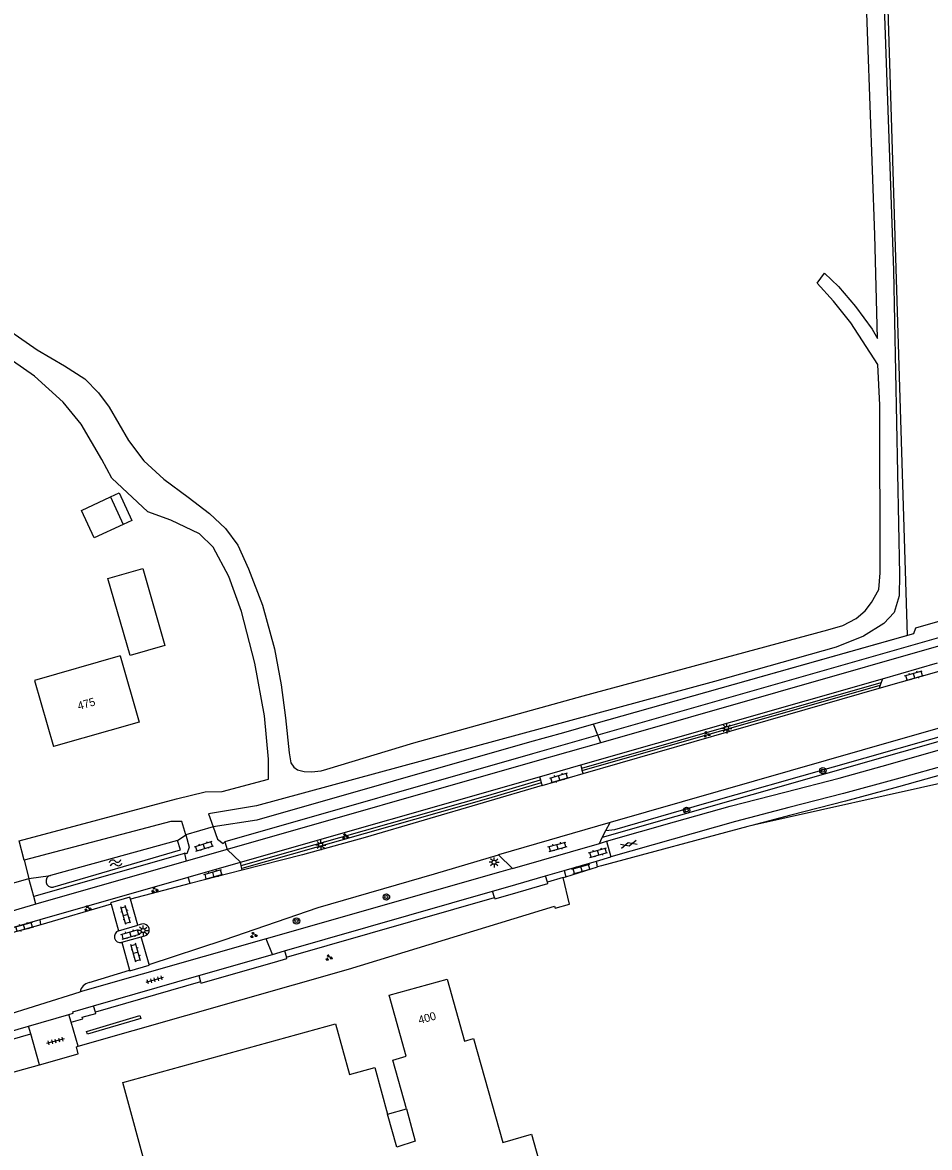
# Model space of a CAD drawing. Extents: x 124000 to 129000, y 395500 to 397503.
# Drawn here: x 127722.2 to 127835.6, y 395651.7 to 395792.3 of the extents above; entities that cross this region are included whole.
import ezdxf

# ---------------------------------------------------------------- set-up
doc = ezdxf.new("R2010")
doc.units = 0
for name, color, linetype in [('gg-afsc-hekwerk', 7, 'Continuous'), ('gg-anno-huisnummerreeks BGT', 7, 'Continuous'), ('gg-bbg-bijgebouw', 7, 'Continuous'), ('gg-bbg-gedigitaliseerde bebouwing', 7, 'Continuous'), ('gg-bbg-gedigitaliseerde bijgebouw', 7, 'Continuous'), ('gg-bbg-hoofdgebouw', 7, 'Continuous'), ('gg-bbg-luifel en loopbrug', 7, 'Continuous'), ('gg-knt-onverhard', 7, 'Continuous'), ('gg-knt-verharding', 7, 'Continuous'), ('gg-kntw-bovenkant insteek waterloop', 7, 'Continuous'), ('gt-grn-groengrens', 7, 'Continuous'), ('gt-grn-groengrens NZ', 7, 'Continuous'), ('gt-grn-weggrens', 7, 'Continuous'), ('gt-symb-boom', 7, 'Continuous'), ('gt-symb-gesloten verharding', 7, 'Continuous'), ('gt-symb-groenvak', 7, 'Continuous'), ('gt-symb-klinker verharding', 7, 'Continuous'), ('gt-symb-lichtmast', 7, 'Continuous'), ('gt-symb-tegel verharding', 7, 'Continuous'), ('gt-symb-watersymbool', 7, 'Continuous')]:
    doc.layers.add(name, color=color, linetype=linetype)

# ---------------------------------------------------------------- blocks, each defined once
blk = doc.blocks.new('gt0-KL1')
at = {"layer": 'gt-symb-klinker verharding'}
for p, q in [((-1.15, 0.3), (1.15, 0.3)), ((-1, -0.3), (-1, 0.3)), ((-0.5, 0.3), (-0.5, 0.45)), ((0, -0.3), (0, 0.3)), ((0.5, 0.3), (0.5, 0.45)), ((1, -0.3), (1, 0.3)), ((-1.15, -0.3), (1.15, -0.3)), ((-0.5, -0.45), (-0.5, -0.3)), ((0.5, -0.45), (0.5, -0.3))]:
    blk.add_line(p, q, dxfattribs=at)
blk = doc.blocks.new('gt0-TEG1')
at = {"layer": 'gt-symb-tegel verharding'}
for p, q in [((-1.12, 0), (1.13, 0)), ((-0.9, -0.25), (-0.9, 0.25)), ((-0.45, -0.25), (-0.45, 0.25)), ((0, -0.25), (0, 0.25)), ((0.45, -0.25), (0.45, 0.25)), ((0.9, -0.25), (0.9, 0.25))]:
    blk.add_line(p, q, dxfattribs=at)
blk = doc.blocks.new('gt0-BOOM')
at = {"layer": 'gt-symb-boom'}
for radius in [0.4, 0.2]:
    blk.add_circle((0, 0), radius, dxfattribs=at)
blk = doc.blocks.new('gt0-GESVH1')
at = {"layer": 'gt-symb-gesloten verharding'}
for p, q in [((-0.99, -0.26), (0.01, 0.24)), ((0.01, -0.26), (-0.99, 0.24)), ((0.01, 0.24), (1.01, -0.26)), ((1.01, 0.24), (0.01, -0.26))]:
    blk.add_line(p, q, dxfattribs=at)
blk = doc.blocks.new('gt0-GRVAK')
at = {"layer": 'gt-symb-groenvak'}
for p, q in [((-0.11, 0.19), (-0.23, 0.24)), ((-0.18, 0.15), (0.09, 0.15)), ((-0.09, 0.21), (-0.16, 0.32)), ((-0.05, 0.21), (-0.05, 0.39)), ((0, 0.21), (0.06, 0.32)), ((0.01, 0.19), (0.13, 0.24)), ((0.26, -0.05), (0.2, 0.06)), ((0.3, -0.05), (0.3, 0.13)), ((0.35, -0.05), (0.41, 0.06)), ((-0.25, -0.23), (-0.36, -0.18)), ((-0.32, -0.26), (-0.05, -0.26)), ((-0.23, -0.21), (-0.29, -0.09)), ((-0.18, -0.2), (-0.18, -0.02)), ((-0.14, -0.21), (-0.07, -0.09)), ((-0.12, -0.23), (0, -0.18)), ((0.24, -0.07), (0.12, -0.02)), ((0.17, -0.11), (0.44, -0.11)), ((0.37, -0.07), (0.49, -0.02))]:
    blk.add_line(p, q, dxfattribs=at)
blk = doc.blocks.new('gt0-LMAST')
at = {"layer": 'gt-symb-lichtmast'}
for p, q in [((-0.18, 0.17), (-0.45, 0.44)), ((-0.01, 0.25), (-0.01, 0.62)), ((0.17, 0.17), (0.44, 0.44)), ((-0.26, 0), (-0.63, 0)), ((-0.18, -0.18), (-0.45, -0.45)), ((-0.01, -0.25), (-0.01, -0.63)), ((0.44, -0.45), (0.17, -0.18)), ((0.24, 0), (0.62, 0))]:
    blk.add_line(p, q, dxfattribs=at)
blk.add_circle((-0.01, 0), 0.25, dxfattribs=at)
blk = doc.blocks.new('gt0-WA')
at = {"layer": 'gt-symb-watersymbool'}
for centre, start, end in [((-0.32, 0.02), 28.0725, 151.9275), ((0.43, 0.42), 208.0725, 331.9275), ((-0.32, -0.43), 28.0725, 151.9275), ((0.43, -0.03), 208.0725, 331.9275)]:
    blk.add_arc(centre, 0.425, start, end, dxfattribs=at)

msp = doc.modelspace()

# ---------------------------------------------------------------- linework, layer by layer
at = {"layer": 'gg-afsc-hekwerk'}
for p, q in [((127833.56, 395715.9), (127793.59, 395704.6)), ((127832.82, 395715.69), (127793.59, 395704.6)), ((127833.56, 395715.9), (127832.82, 395715.69)), ((127793.59, 395704.6), (127789.82, 395703.54)), ((127793.59, 395704.6), (127789.82, 395703.54)), ((127789.82, 395703.54), (127785.57, 395702.36)), ((127789.82, 395703.54), (127785.57, 395702.36)), ((127867.01, 395703.93), (127813.34, 395691.94)), ((127746.06, 395691.8), (127742.62, 395690.8)), ((127746.06, 395691.8), (127742.62, 395690.8)), ((127790.13, 395685.55), (127794.07, 395686.77)), ((127789.77, 395685.44), (127790.13, 395685.55))]:
    msp.add_line(p, q, dxfattribs=at)
for points in [[(127926.73, 395743.24), (127884.31, 395731.12), (127883.52, 395734.03), (127880.23, 395733.04), (127881.06, 395730.15), (127833.81, 395716.63), (127833.56, 395715.9)], [(127880.23, 395733.04), (127881.06, 395730.15), (127833.81, 395716.63), (127833.56, 395715.9)], [(127785.57, 395702.36), (127751.51, 395692.62), (127746.06, 395691.8)], [(127785.57, 395702.36), (127751.51, 395692.62), (127746.06, 395691.8)], [(127813.34, 395691.94), (127812.84, 395691.83), (127794.55, 395686.92), (127794.07, 395686.77)], [(127729.16, 395664.36), (127762.95, 395674), (127788.68, 395681.85), (127788.76, 395681.62), (127790.57, 395682.14), (127789.77, 395685.44)], [(127724.35, 395662.06), (127729.18, 395663.4), (127728.95, 395664.3), (127729.16, 395664.36)], [(127714.67, 395660.36), (127714.96, 395659.46), (127724.35, 395662.06)]]:
    msp.add_lwpolyline(points, dxfattribs=at)
at = {"layer": 'gg-bbg-bijgebouw'}
msp.add_line((127740.01, 395714.45), (127735.67, 395713.2), dxfattribs=at)
at = {"layer": 'gg-bbg-gedigitaliseerde bebouwing'}
msp.add_lwpolyline([(127734.41, 395713.14), (127723.74, 395710.08), (127726.08, 395701.84)], dxfattribs=at)
at = {"layer": 'gg-bbg-gedigitaliseerde bijgebouw'}
msp.add_line((127733.2, 395733.01), (127734.81, 395729.57), dxfattribs=at)
for points in [[(127734.81, 395729.57), (127731.19, 395727.88), (127729.58, 395731.32), (127733.2, 395733.01)], [(127735.67, 395713.2), (127732.9, 395722.81), (127737.24, 395724.06), (127740.01, 395714.45)]]:
    msp.add_lwpolyline(points, dxfattribs=at)
at = {"layer": 'gg-bbg-hoofdgebouw'}
for points in [[(127734.41, 395713.14), (127736.78, 395704.88), (127726.08, 395701.84)], [(127770.19, 395656.53), (127768.51, 395662.62), (127770.18, 395663.11), (127768.02, 395670.74), (127775.3, 395672.76), (127777.44, 395665), (127778.58, 395665.35), (127782.24, 395652.34), (127785.82, 395653.36), (127787.38, 395647.89)], [(127737.94, 395648.22), (127734.74, 395659.83), (127761.34, 395667.16), (127763.09, 395660.82), (127766.24, 395661.69), (127767.84, 395655.88)], [(127770.19, 395656.53), (127771.3, 395652.49), (127768.98, 395651.76), (127767.84, 395655.88)]]:
    msp.add_lwpolyline(points, dxfattribs=at)
at = {"layer": 'gg-bbg-luifel en loopbrug'}
msp.add_line((127767.84, 395655.88), (127770.19, 395656.53), dxfattribs=at)
msp.add_lwpolyline([(127733.2, 395733.01), (127734.28, 395733.52), (127735.9, 395730.08), (127734.81, 395729.57)], dxfattribs=at)
at = {"layer": 'gg-knt-onverhard'}
msp.add_line((127722.45, 395687.61), (127723.01, 395685.31), dxfattribs=at)
for points in [[(127821.9, 395982.58), (127826.07, 395878.37), (127827.36, 395860.58), (127829.47, 395806.14), (127831.06, 395761.29), (127831.82, 395723.3), (127831.76, 395720.66), (127831.12, 395718.55), (127829.83, 395717.2), (127827.3, 395715.61), (127823.87, 395714.24), (127808.67, 395709.95), (127751.47, 395694.41), (127745.46, 395693.4), (127746.06, 395691.8)], [(127718.4, 395755.29), (127724.04, 395751.39), (127727.46, 395749.41), (127730, 395747.77), (127731.7, 395746.02), (127733.04, 395744.25), (127735.47, 395740.05), (127737.37, 395737.51), (127739.88, 395735.24), (127742.91, 395732.98), (127745.57, 395730.93), (127747.6, 395729.05), (127749.13, 395727), (127750.47, 395724.03), (127752.22, 395719.5), (127753.73, 395714.02), (127754.56, 395709.55), (127755.08, 395705.39), (127755.54, 395701.04), (127755.73, 395699.78), (127756.13, 395699.24), (127756.6, 395698.9), (127757.41, 395698.71), (127758.35, 395698.66), (127759.56, 395698.78), (127760.24, 395699.01), (127771.13, 395702.29), (127792.28, 395708.15), (127822.87, 395716.41), (127824.74, 395716.96), (127826.39, 395717.82), (127827.52, 395718.77), (127828.29, 395719.81), (127829.21, 395721.43), (127829.39, 395723.51), (127829.35, 395744.48), (127829.11, 395749.55), (127825.74, 395754.76), (127823.57, 395757.48), (127821.52, 395759.72), (127822.44, 395760.97), (127824.18, 395759.32), (127826.29, 395756.81), (127828.37, 395753.96), (127829.05, 395752.8), (127828.71, 395765.78), (127826.96, 395814.29)], [(127722.45, 395687.61), (127721.8, 395690.02), (127741.46, 395695.27), (127745.06, 395696.16), (127747.15, 395696.19), (127752.96, 395697.72), (127752.96, 395700.26), (127752.47, 395705.64), (127751.24, 395712.25), (127749.59, 395718.71), (127747.99, 395723.08), (127746.04, 395726.72), (127744.32, 395728.4), (127740.77, 395730.09), (127737.87, 395731.13), (127733.4, 395735.35), (127732.14, 395737.68), (127729.56, 395742.09), (127727.31, 395744.87), (127723.73, 395748.09), (127716.82, 395752.91)], [(127742.62, 395690.8), (127742.13, 395692.45), (127740.76, 395692.45), (127722.45, 395687.61)]]:
    msp.add_lwpolyline(points, dxfattribs=at)
at = {"layer": 'gg-knt-verharding'}
for p, q in [((127927.82, 395740.45), (127794.49, 395702.3)), ((127829.26, 395709.1), (127837.36, 395711.41)), ((127829.67, 395710.29), (127836.55, 395712.26)), ((127792, 395699.52), (127829.67, 395710.29)), ((127829.51, 395709.84), (127829.39, 395709.48)), ((127829.67, 395710.29), (127829.51, 395709.84)), ((127792.27, 395698.43), (127829.26, 395709.1)), ((127829.39, 395709.48), (127829.26, 395709.1)), ((127794.49, 395702.3), (127786.22, 395699.94)), ((127786.22, 395699.94), (127747.81, 395688.95)), ((127786.82, 395698.04), (127792, 395699.52)), ((127787.14, 395696.95), (127792.27, 395698.43)), ((127792.1, 395699.13), (127792, 395699.52)), ((127792.17, 395698.83), (127792.1, 395699.13)), ((127792.27, 395698.43), (127792.17, 395698.83)), ((127749.45, 395687.35), (127786.82, 395698.04)), ((127786.82, 395698.04), (127786.93, 395697.65)), ((127786.93, 395697.65), (127787.04, 395697.27)), ((127787.04, 395697.27), (127787.14, 395696.95)), ((127795.64, 395692.33), (127781.69, 395688.29)), ((127794.67, 395690.44), (127795.12, 395691.31)), ((127795.12, 395691.31), (127795.64, 395692.33)), ((127794.3, 395689.72), (127794.67, 395690.44)), ((127794.3, 395689.72), (127795.21, 395689.98)), ((127795.21, 395689.98), (127795.74, 395688.04)), ((127747.81, 395688.95), (127742.69, 395687.48)), ((127747.5, 395689.9), (127747.81, 395688.95)), ((127783.46, 395686.58), (127794.3, 395689.72)), ((127742.69, 395687.48), (127723.89, 395682.1)), ((127742.45, 395688.45), (127742.69, 395687.48)), ((127742.91, 395685.48), (127749.45, 395687.35)), ((127749.54, 395686.95), (127749.45, 395687.35)), ((127783.46, 395686.58), (127781.69, 395688.29)), ((127789.89, 395686.33), (127793.94, 395687.51)), ((127793.94, 395687.51), (127795.74, 395688.04)), ((127794.07, 395686.77), (127793.94, 395687.51)), ((127749.69, 395686.37), (127743.17, 395684.69)), ((127749.64, 395686.58), (127749.54, 395686.95)), ((127749.69, 395686.37), (127749.64, 395686.58)), ((127787.59, 395685.66), (127789.89, 395686.33)), ((127789.89, 395686.33), (127790.13, 395685.55)), ((127723.62, 395683.06), (127723.01, 395685.31)), ((127724.41, 395680.19), (127742.91, 395685.48)), ((127743.17, 395684.69), (127735.71, 395682.74)), ((127743.17, 395684.69), (127742.91, 395685.48)), ((127780.96, 395683.75), (127782.87, 395684.29)), ((127782.87, 395684.29), (127787.59, 395685.66)), ((127723.89, 395682.1), (127723.62, 395683.06)), ((127754.98, 395676.29), (127780.96, 395683.75)), ((127723.89, 395682.1), (127719.17, 395680.75)), ((127733.29, 395682.1), (127724.5, 395679.55)), ((127733.29, 395682.1), (127734.23, 395678.78)), ((127736.63, 395679.48), (127735.71, 395682.74)), ((127719.69, 395678.84), (127724.41, 395680.19)), ((127724.5, 395679.55), (127724.41, 395680.19)), ((127724.5, 395679.55), (127719.84, 395678.26)), ((127734.23, 395678.78), (127736.63, 395679.48)), ((127737.1, 395679.61), (127736.63, 395679.48)), ((127752.67, 395677.79), (127729.41, 395671.16)), ((127734.62, 395677.35), (127737.04, 395678.04)), ((127734.62, 395677.35), (127735.61, 395673.86)), ((127737.04, 395678.04), (127737.5, 395678.16)), ((127738.03, 395674.59), (127737.04, 395678.04)), ((127744.25, 395673.21), (127753.45, 395675.85)), ((127753.45, 395675.85), (127754.98, 395676.29)), ((127730.54, 395672.33), (127735.61, 395673.86)), ((127731.11, 395669.43), (127744.25, 395673.21)), ((127719.3, 395667.98), (127729.41, 395671.16)), ((127722.99, 395666.88), (127728.03, 395668.34)), ((127728.31, 395667.38), (127728.03, 395668.34)), ((127713.62, 395664.15), (127722.99, 395666.88)), ((127723.26, 395665.91), (127722.99, 395666.88)), ((127729.16, 395664.36), (127728.31, 395667.38)), ((127724.35, 395662.06), (127723.26, 395665.91))]:
    msp.add_line(p, q, dxfattribs=at)
for points in [[(128045.51, 395763.75), (127968.1, 395741.55), (127831.64, 395702.64), (127795.64, 395692.33)], [(127795.21, 395689.98), (127803.68, 395692.4), (127810.64, 395694.36), (127817.47, 395696.11), (127824.26, 395697.87), (127830.68, 395699.64), (127943.99, 395732.06), (127979.56, 395742.19), (128046.08, 395761.21)], [(128046.53, 395759.25), (127980.17, 395740.24), (127908.75, 395719.89), (127873.12, 395709.69), (127838.24, 395699.67), (127831.4, 395697.73), (127824.82, 395695.95), (127817.97, 395694.22), (127811.33, 395692.44), (127795.74, 395688.04)], [(127787.14, 395696.95), (127765.04, 395690.47), (127757.19, 395688.28), (127749.69, 395686.37)], [(127746.06, 395691.8), (127746.6, 395690.26), (127747.3, 395689.69), (127747.5, 395689.91), (127747.5, 395689.9)], [(127742.62, 395690.8), (127743.04, 395689.23), (127742.77, 395688.4), (127742.44, 395688.48), (127742.45, 395688.45)], [(127738.03, 395674.59), (127747.42, 395677.67), (127759.18, 395681.72), (127773.7, 395685.93), (127781.69, 395688.29)], [(127783.46, 395686.58), (127781.99, 395686.15), (127752.67, 395677.79)], [(127735.71, 395682.74), (127735.64, 395683), (127733.23, 395682.3), (127733.29, 395682.1)], [(127735.61, 395673.86), (127735.63, 395673.79), (127738.06, 395674.49), (127738.03, 395674.59)], [(127728.03, 395668.34), (127728.56, 395668.49), (127728.51, 395668.68), (127731.11, 395669.43)]]:
    msp.add_lwpolyline(points, dxfattribs=at)
for centre, radius, start, end in [((127734.44, 395678.07), 0.743, 106.3546, 284.1692), ((127737.31, 395678.89), 0.752, 284.1669, 106.4569), ((127730.88, 395670.87), 1.5, 103.3629, 168.8817)]:
    msp.add_arc(centre, radius, start, end, dxfattribs=at)
at = {"layer": 'gg-kntw-bovenkant insteek waterloop'}
msp.add_line((127741.61, 395690.08), (127725.74, 395685.72), dxfattribs=at)
msp.add_lwpolyline([(127726.03, 395684.26), (127741.96, 395688.9), (127741.61, 395690.08)], dxfattribs=at)
msp.add_arc((127725.9, 395684.99), 0.749, 102.2701, 280.4548, dxfattribs=at)
at = {"layer": 'gt-grn-groengrens'}
for p, q in [((127792.1, 395699.13), (127829.51, 395709.84)), ((127792.17, 395698.83), (127829.39, 395709.48)), ((127794.12, 395703.24), (127793.59, 395704.6)), ((127794.49, 395702.3), (127794.12, 395703.24)), ((127741.61, 395690.08), (127742.62, 395690.8)), ((127723.01, 395685.31), (127725.74, 395685.72)), ((127787.82, 395684.88), (127787.59, 395685.66)), ((127789.77, 395685.44), (127787.82, 395684.88)), ((127755.21, 395675.49), (127781.19, 395682.96)), ((127781.19, 395682.96), (127780.96, 395683.75)), ((127754.98, 395676.29), (127755.21, 395675.49)), ((127744.25, 395673.21), (127744.47, 395672.41)), ((127744.47, 395672.41), (127731.34, 395668.64)), ((127731.34, 395668.64), (127731.11, 395669.43))]:
    msp.add_line(p, q, dxfattribs=at)
for points in [[(127832.82, 395715.69), (127829.42, 395824.99), (127822.11, 396018.45), (127815.88, 396054.94)], [(127795.12, 395691.31), (127796.23, 395691.46), (127807.42, 395694.68), (127855.81, 395708.46), (127939.09, 395732.22), (127939.32, 395731.83), (127894.36, 395718.86), (127873.56, 395712.95), (127867.62, 395711.25), (127859.96, 395709.07), (127794.67, 395690.44)], [(127749.54, 395686.95), (127780.35, 395695.72), (127786.93, 395697.65)], [(127787.04, 395697.27), (127780.45, 395695.33), (127749.64, 395686.58)], [(127730.21, 395666.21), (127736.9, 395668.2), (127737.02, 395667.84), (127730.35, 395665.86), (127730.21, 395666.21)]]:
    msp.add_lwpolyline(points, dxfattribs=at)
at = {"layer": 'gt-grn-groengrens NZ'}
for p, q in [((127886.32, 395729.62), (127794.12, 395703.24)), ((127794.12, 395703.24), (127785.95, 395700.9)), ((127785.95, 395700.9), (127747.5, 395689.9)), ((127742.45, 395688.45), (127723.62, 395683.06)), ((127713.89, 395663.19), (127723.26, 395665.91))]:
    msp.add_line(p, q, dxfattribs=at)
for points in [[(128046.74, 395758.28), (127980.45, 395739.27), (127909.02, 395718.93), (127873.4, 395708.73), (127838.51, 395698.71), (127831.67, 395696.77), (127825.07, 395694.98), (127818.22, 395693.25), (127813.34, 395691.94)], [(127783.15, 395683.33), (127787.87, 395684.7), (127787.82, 395684.88)], [(127781.19, 395682.96), (127781.23, 395682.79), (127783.15, 395683.33)], [(127744.47, 395672.41), (127744.52, 395672.24), (127753.72, 395674.89)], [(127753.72, 395674.89), (127755.26, 395675.33), (127755.21, 395675.49)], [(127728.31, 395667.38), (127729.74, 395667.79), (127729.69, 395667.98), (127731.38, 395668.47), (127731.34, 395668.64)]]:
    msp.add_lwpolyline(points, dxfattribs=at)
at = {"layer": 'gt-grn-weggrens'}
for p, q in [((127749.45, 395687.35), (127747.81, 395688.95)), ((127718.27, 395683.98), (127723.01, 395685.31)), ((127753.45, 395675.85), (127752.67, 395677.79))]:
    msp.add_line(p, q, dxfattribs=at)

# ---------------------------------------------------------------- block references
at = {"layer": 'gt-symb-boom'}
for p in [(127822.23, 395698.8), (127805.21, 395693.84), (127767.69, 395683.01), (127756.46, 395680.02)]:
    msp.add_blockref('gt0-BOOM', p, dxfattribs=at)
at = {"layer": 'gt-symb-gesloten verharding', "rotation": 14.481034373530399}
msp.add_blockref('gt0-GESVH1', (127797.97, 395689.61), dxfattribs=at)
at = {"layer": 'gt-symb-groenvak'}
for p in [(127807.7, 395703.33), (127762.55, 395690.57), (127738.71, 395683.91), (127730.36, 395681.58), (127751.09, 395678.25), (127760.5, 395675.44)]:
    msp.add_blockref('gt0-GRVAK', p, dxfattribs=at)
at = {"layer": 'gt-symb-klinker verharding'}
for p, rotation in [((127833.62, 395710.67), 16.079172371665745), ((127789.29, 395697.91), 16.07917237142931), ((127744.9, 395689.35), 17.09430559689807), ((127789.07, 395689.3), 14.953564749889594), ((127794.15, 395688.56), 15.551724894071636), ((127792.07, 395686.52), 16.07917237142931), ((127746.07, 395685.85), 15.189787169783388), ((127735.1, 395680.76), 106.07917237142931), ((127722.43, 395679.28), 15.425970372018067), ((127735.7, 395678.35), 15.425970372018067), ((127736.37, 395676.05), 106.07917237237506)]:
    msp.add_blockref('gt0-KL1', p, dxfattribs=dict(at, rotation=rotation))
at = {"layer": 'gt-symb-lichtmast'}
for p in [(127810.22, 395704.09), (127759.5, 395689.51), (127781.16, 395687.35), (127737.3, 395678.82)]:
    msp.add_blockref('gt0-LMAST', p, dxfattribs=at)
at = {"layer": 'gt-symb-tegel verharding'}
for p, rotation in [((127738.75, 395672.67), 16.02410965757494), ((127726.33, 395665.02), -164.9910863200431)]:
    msp.add_blockref('gt0-TEG1', p, dxfattribs=dict(at, rotation=rotation))
at = {"layer": 'gt-symb-watersymbool', "rotation": -165.04643525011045}
msp.add_blockref('gt0-WA', (127733.9, 395687.28), dxfattribs=at)

# ---------------------------------------------------------------- texts
at = {"layer": 'gg-anno-huisnummerreeks BGT'}
for s, rotation, p in [('475', 15.9, (127729.26, 395706.38)), ('400', 15.5, (127771.83, 395667.13))]:
    msp.add_text(s, height=1, rotation=rotation, dxfattribs=at).set_placement(p)

doc.saveas('drawing.dxf')
